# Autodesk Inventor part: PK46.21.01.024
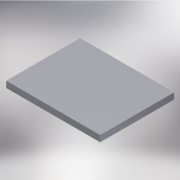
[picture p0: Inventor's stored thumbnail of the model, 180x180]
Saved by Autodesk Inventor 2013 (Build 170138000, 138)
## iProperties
Created: 2005-04
Part Number: PK46.21.01.024
Material: Steel, Mild
Document SubType Name: Modeling
Designer: salex
Manufacturer: Standard
Standards Organization: Custom
Density: 7.86 g/cm^3
Author: salex
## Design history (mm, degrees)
sketch "Эскиз1"
  geometry: L1 (0, 0)-(150, 0); L2 (150, 0)-(150, 118); L3 (150, 118)-(0, 118); L4 (0, 118)-(0, 0)
  constraints: 8 end point, 2 parallel, 1 horizontal, 1 perpendicular, 1 other
  dimensions: "d0" = 150 distance of L1.start L1.end; "d1" = 118 distance of L3.end L1.start
extrude "Выдавливание1" new body sketch "Эскиз1" distance "d2" = 10; taper "d3" = 0 deg
body "Solid1"
